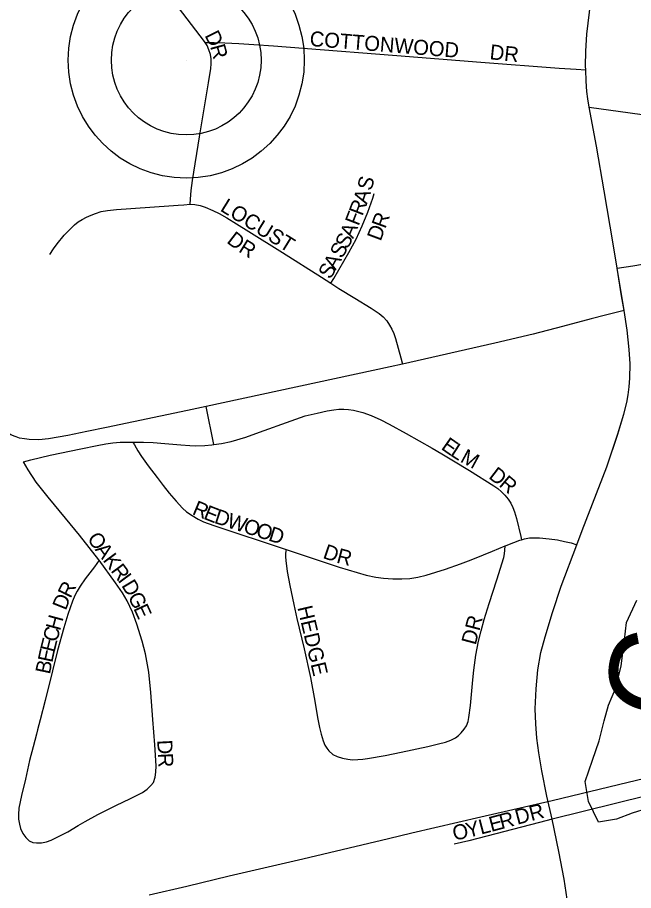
# Model space of a CAD drawing. Extents: x 1410790 to 1770854, y 566777 to 831614.
# Drawn here: x 1585877 to 1587927, y 704996 to 707901 of the extents above; entities that cross this region are included whole.
import ezdxf

# ---------------------------------------------------------------- set-up
doc = ezdxf.new("R2010")
doc.units = 0
for name, color, linetype in [('GM_X_City_Street', 7, 'Continuous'), ('GM_X_Corporation', 7, 'Continuous'), ('GM_X_County_Road', 7, 'Continuous'), ('GM_X_County_Road_Text', 7, 'Continuous'), ('GM_X_Minor_River', 7, 'Continuous'), ('GM_X_Rail_Line', 7, 'Continuous'), ('GM_X_Township_Subdivision', 7, 'Continuous'), ('GM_X_Township_Subdivision_Text', 7, 'Continuous'), ('GM_X_Unincorporated', 7, 'Continuous'), ('GM_X_Unincorporated_Location', 7, 'Continuous')]:
    doc.layers.add(name, color=color, linetype=linetype)

msp = doc.modelspace()

# ---------------------------------------------------------------- linework, layer by layer
at = {"layer": 'GM_X_City_Street'}
msp.add_lwpolyline([(1587872.1, 707066.5), (1587923.8, 707075.1), (1588014.1, 707090.2)], dxfattribs=at)
at = {"layer": 'GM_X_Corporation'}
msp.add_lwpolyline([(1588288.3, 705389.6), (1587655.6, 705233.1), (1587637.8, 705310.2), (1587621.4, 705393.9), (1587611.2, 705454.2), (1587605, 705502.7), (1587601, 705551.2), (1587599.5, 705600.5), (1587602.6, 705667), (1587608.1, 705730.4), (1587618.3, 705787.5), (1587633.1, 705840.7), (1587656.6, 705921.3), (1587686.3, 706008.9), (1587738, 706146.5), (1587756, 706194.3), (1587837.3, 706405.6), (1587874.9, 706515.1), (1587894.8, 706581), (1587904, 706619.5), (1587908.5, 706645), (1587912.4, 706672.4), (1587914.8, 706701.4), (1587915.6, 706748.3), (1587912.4, 706796.8), (1587906, 706861.1), (1587895.2, 706926.2), (1587872.1, 707066.5), (1587871.8, 707068.3), (1587848.9, 707206.6), (1587829.3, 707324.9), (1587802.9, 707472.6), (1587779.4, 707602.7), (1588156.3, 707550.7)], dxfattribs=at)
at = {"layer": 'GM_X_County_Road'}
for points in [[(1587767.4, 707726.7), (1587766.8, 707739.3), (1587767.4, 707789.5), (1587771.3, 707846.2), (1587793.7, 708030.3), (1587820.4, 708230.3), (1587824.5, 708261.2)], [(1587872.1, 707066.5), (1587871.8, 707068.3), (1587848.9, 707206.6), (1587829.3, 707324.9), (1587802.9, 707472.6), (1587779.4, 707602.7), (1587774.4, 707630), (1587771.4, 707655.2), (1587768.9, 707689.2), (1587767.4, 707726.7)], [(1586504.2, 706606.8), (1586442.1, 706593.4), (1586173, 706537), (1586107.8, 706523.9), (1586043.8, 706510.5), (1585979.6, 706499), (1585947.5, 706496), (1585915.4, 706496.7), (1585899.5, 706498.7), (1585883.8, 706501.7), (1585872.2, 706505.2), (1585868.7, 706506.3), (1585854.4, 706512.6), (1585840.9, 706520.8), (1585815.4, 706540.6), (1585791.7, 706562.8), (1585758.7, 706598.7), (1585714.7, 706654.2), (1585598.5, 706808.4), (1585507.2, 706925), (1585418.7, 707042.2), (1585306.7, 707183.7), (1585284.6, 707211.2)], [(1587895.2, 706926.1), (1587887, 706974.8), (1587872.1, 707066.5)], [(1587895.2, 706926.1), (1587833, 706910.2), (1587785.4, 706898), (1587690.8, 706872.4), (1587593.2, 706847.8), (1587465.6, 706817.4), (1587158.4, 706747.9)], [(1587738, 706146.5), (1587756, 706194.4), (1587837.3, 706405.6), (1587874.9, 706515.2), (1587894.8, 706581), (1587904, 706619.5), (1587908.5, 706645), (1587912.4, 706672.4), (1587914.8, 706701.3), (1587915.6, 706748.3), (1587912.4, 706796.8), (1587906, 706861.1), (1587895.2, 706926.1)], [(1587158.4, 706747.9), (1587117, 706738.5), (1586504.2, 706606.8)], [(1587655.6, 705233.1), (1587637.8, 705310.2), (1587621.4, 705393.9), (1587611.2, 705454.2), (1587605, 705502.7), (1587601.1, 705551.2), (1587599.5, 705600.5), (1587602.6, 705667), (1587608.1, 705730.4), (1587618.2, 705787.5), (1587633.1, 705840.7), (1587656.6, 705921.3), (1587686.3, 706008.9), (1587738, 706146.5)], [(1587703.7, 704682.8), (1587706.7, 704719.5), (1587714.4, 704820.2), (1587714.7, 704869.2), (1587711.4, 704921.4), (1587705.9, 704966.7), (1587695.7, 705033.2), (1587677.7, 705126.3), (1587655.6, 705233.1)]]:
    msp.add_lwpolyline(points, dxfattribs=at)
at = {"layer": 'GM_X_Minor_River'}
msp.add_lwpolyline([(1587972.2, 705268.7), (1587922.1, 705253.1), (1587870.1, 705233.4), (1587810.1, 705223.8), (1587776.6, 705292.2), (1587765.2, 705358.4), (1587789.7, 705430.3), (1587812.2, 705494.3), (1587828.7, 705560.3), (1587843, 705612.3), (1587867.5, 705670.2), (1587886, 705744.2), (1587896.7, 705830.3), (1587903.1, 705888.4), (1587937.7, 705962.3)], dxfattribs=at)
at = {"layer": 'GM_X_Rail_Line'}
msp.add_lwpolyline([(1586314.4, 704981.6), (1586440.7, 705010.3), (1586581.4, 705044.5), (1586825.9, 705101), (1587111.5, 705168.8), (1587189, 705188.3), (1587418, 705241.3), (1587656.2, 705296), (1587909.3, 705356.5), (1588113, 705405.4)], dxfattribs=at)
at = {"layer": 'GM_X_Township_Subdivision'}
for points in [[(1586501, 707818.4), (1586499.2, 707821.5), (1586383.7, 707973.6), (1586333.5, 708045.2), (1586296.5, 708099.5), (1586270.4, 708141.3), (1586252.8, 708173.1)], [(1586451.1, 707279.8), (1586452.1, 707296.4), (1586454.6, 707326), (1586458.6, 707358.8), (1586482, 707504.2), (1586512.6, 707683.9), (1586520.5, 707731.4), (1586521.4, 707747.3), (1586520.9, 707763.1), (1586518.4, 707778.6), (1586513.9, 707793.6), (1586507.4, 707807.9), (1586501, 707818.4)], [(1586501, 707818.4), (1586531.6, 707817.8), (1586566.2, 707816.9), (1586613.2, 707814.6), (1586662.7, 707811.7), (1586728.6, 707807), (1586827.1, 707798.9), (1587138.8, 707774.7), (1587418.2, 707752.1), (1587679.5, 707733.1), (1587736.3, 707729), (1587767.4, 707726.7)], [(1586919.8, 707016.6), (1586929.2, 707032.8), (1586979.4, 707118.8), (1587003.6, 707163.4), (1587023.8, 707208.1), (1587042.5, 707253.6), (1587058.9, 707300), (1587063.8, 707315.5)], [(1585984.5, 707112.7), (1585996.7, 707131.2), (1586009.2, 707148.4), (1586031.8, 707177.1), (1586052.5, 707198.2), (1586066.1, 707210.8), (1586078.6, 707220.7), (1586092.2, 707229.4), (1586106.8, 707237), (1586121.4, 707243.5), (1586136, 707249), (1586155.1, 707255.1), (1586176.3, 707259.1), (1586206.5, 707262.7), (1586379.9, 707273.9), (1586411.3, 707276.7), (1586430.4, 707278.2), (1586451.1, 707279.8)], [(1586451.1, 707279.8), (1586467.2, 707278.8), (1586484.3, 707275.7), (1586500.9, 707270.2), (1586526.6, 707259.1), (1586548.2, 707248.6), (1586573.4, 707234), (1586605.6, 707214.8), (1586646.3, 707189.2), (1586758, 707118.7), (1586887.9, 707036.7), (1586919.8, 707016.6)], [(1586919.8, 707016.6), (1586946.3, 706999.9), (1586999.6, 706967.7), (1587054, 706933.5), (1587079.7, 706915.9), (1587093.2, 706904.8), (1587105.3, 706891.7), (1587114.9, 706877.1), (1587122.4, 706863.5), (1587129, 706849.4), (1587135, 706833.4), (1587152.6, 706768.9), (1587158.4, 706747.9)], [(1586530.2, 706480.6), (1586504.2, 706606.8)], [(1586530.2, 706480.6), (1586555.2, 706483.8), (1586587.2, 706490.1), (1586636.9, 706504.5), (1586682.4, 706521.1), (1586787.7, 706559.4), (1586834, 706575.2), (1586873.5, 706585), (1586906.8, 706592.8), (1586929, 706596.1), (1586945.9, 706597.8), (1586962.2, 706597.9), (1586978.6, 706596.9), (1586994.9, 706594.6), (1587025.4, 706587.2), (1587053.9, 706576.5), (1587086.2, 706562.2), (1587113.4, 706548.4), (1587170.2, 706517.3), (1587256.7, 706468.4), (1587289, 706448.9), (1587327.8, 706426.1), (1587381.2, 706393.9), (1587461.3, 706343.1), (1587474.7, 706333.5), (1587487.3, 706322.9), (1587498.8, 706311.3), (1587509.2, 706298.7), (1587518, 706285), (1587525.5, 706270.6), (1587531.1, 706255.6), (1587537.2, 706234.5), (1587551.7, 706174), (1587554.2, 706163.4)], [(1585896.2, 706422.6), (1585921.5, 706428.9), (1585985.3, 706445), (1586087.5, 706466.1), (1586141.4, 706477.3), (1586170.3, 706482.8), (1586193.6, 706486.1), (1586218.6, 706487.8), (1586260.9, 706488.4)], [(1586260.9, 706488.4), (1586295.8, 706487.8), (1586328.1, 706486.7), (1586367.5, 706483.7), (1586420.3, 706478.9), (1586450.2, 706476.7), (1586470.3, 706475.6), (1586500.2, 706477.3), (1586522.9, 706479.6), (1586530.2, 706480.6)], [(1586260.9, 706488.4), (1586265.9, 706479.5), (1586276.9, 706459.5), (1586289.7, 706440), (1586311.7, 706409.4), (1586341.5, 706370.1), (1586361.7, 706344.3), (1586381.8, 706318.7), (1586404.7, 706291.2), (1586425.8, 706268.4), (1586439.1, 706256.2), (1586457.5, 706243.4), (1586478, 706231.8), (1586495.8, 706223.4), (1586529.7, 706210.6), (1586770.8, 706130.3)], [(1586148.3, 706094.8), (1586147.1, 706096.5), (1586082.8, 706178.7), (1586036.4, 706234.8), (1585978.6, 706304.8), (1585938.8, 706355.2), (1585911.9, 706395.9), (1585896.2, 706422.6)], [(1587499.7, 706142.8), (1587502.3, 706143.9), (1587527.8, 706154), (1587548.4, 706161.7), (1587554.2, 706163.4)], [(1587554.2, 706163.4), (1587563.9, 706166.2), (1587580.6, 706169.5), (1587597.2, 706170.1), (1587613.3, 706170.1), (1587646.1, 706166.8), (1587673.9, 706162.9), (1587697.2, 706157.9), (1587718.9, 706153.1), (1587738, 706146.5)], [(1586770.8, 706130.3), (1586768.5, 706118.4), (1586768, 706106.2), (1586769.1, 706094), (1586774.1, 706057.3), (1586782.9, 706011.2), (1586796.3, 705947.9), (1586806.3, 705901.2), (1586830.7, 705800.2), (1586851.3, 705705.2), (1586865.7, 705625.8), (1586875.2, 705571.3), (1586881.8, 705538), (1586887.4, 705516.3), (1586893.5, 705494.1), (1586899.1, 705480.2), (1586905.9, 705469.3), (1586912.4, 705460.8), (1586926.3, 705449.1), (1586940.1, 705442.5), (1586958.5, 705436.4), (1586976.3, 705433), (1586991.2, 705431.4), (1587009.1, 705432.4), (1587025.3, 705433.5), (1587041.4, 705435.4), (1587100.7, 705445.8), (1587153.9, 705456.3), (1587241.7, 705474.7), (1587277.3, 705483.6), (1587301.2, 705490.2), (1587318.4, 705496.3), (1587334.5, 705504.1), (1587343.9, 705511.4), (1587353.4, 705520.2), (1587363.4, 705532.4), (1587370.6, 705544.1), (1587376.2, 705558), (1587378.4, 705571.3), (1587384.4, 705611.2), (1587391.9, 705697.2), (1587394.9, 705729.7), (1587402.3, 705779.1), (1587411.2, 705826.3), (1587419.5, 705859.6), (1587430, 705897.4), (1587446.2, 705950.6), (1587472.3, 706029.6), (1587495.6, 706104.4), (1587497.3, 706116.8), (1587498.4, 706128.4), (1587499.7, 706142.8)], [(1586770.8, 706130.3), (1586946.8, 706071.8), (1587036.8, 706045.1), (1587069, 706038.5), (1587095.1, 706035.7), (1587126.2, 706033.5), (1587155.7, 706032.9), (1587181.8, 706034), (1587209, 706038.5), (1587236.8, 706045.1), (1587300.6, 706065.1), (1587350.6, 706082.9), (1587386.1, 706096.5), (1587427.4, 706113.1), (1587457.3, 706125.8), (1587499.7, 706142.8)], [(1586148.3, 706094.8), (1586132.5, 706073.6), (1586101.5, 706033.1), (1586085.5, 706008.7), (1586074.7, 705991.8), (1586067.7, 705978.1), (1586059.7, 705958.9), (1586043.9, 705914.9), (1586030.3, 705869.8), (1586009.9, 705794.2), (1585992.9, 705727), (1585968.3, 705628.4), (1585952.6, 705563.7), (1585943.3, 705531.1), (1585940, 705516.6), (1585929.1, 705474), (1585916.9, 705428.2), (1585902.8, 705366.6), (1585890.1, 705312.2), (1585880.9, 705270.3), (1585879.6, 705248.8), (1585880.3, 705233.5), (1585882.9, 705217.2), (1585886.8, 705202.8), (1585894, 705186.2), (1585904.4, 705172.4), (1585915.4, 705161.8)], [(1585915.4, 705161.8), (1585927.2, 705155.8), (1585939.9, 705154.2), (1585956.9, 705154.6), (1585972.9, 705158.1), (1585988.3, 705163.6), (1586004.6, 705171.1), (1586044.7, 705191), (1586078.8, 705212.7), (1586101.4, 705226.1), (1586144.1, 705248.5), (1586188, 705271.1), (1586204.3, 705279.1), (1586252.3, 705302.2), (1586292.6, 705322.4), (1586308.2, 705333.5), (1586320.9, 705344.9), (1586329.1, 705355.8), (1586335.2, 705373.7), (1586337.4, 705389.3), (1586337.7, 705410.8), (1586333.4, 705480.7), (1586326.8, 705565.5), (1586320.9, 705655.2), (1586313.9, 705723), (1586302.5, 705783.2), (1586291.1, 705826.3), (1586274, 705882.5), (1586259.3, 705922.4), (1586241.4, 705959.8), (1586226, 705986.6), (1586203.2, 706020), (1586148.3, 706094.8)], [(1587655.6, 705233.1), (1587614, 705222.7), (1587378.9, 705161.6), (1587330.3, 705150.6)]]:
    msp.add_lwpolyline(points, dxfattribs=at)
at = {"layer": 'GM_X_Unincorporated'}
for radius in [392.8, 249]:
    msp.add_circle((1586438.2, 707759.3), radius, dxfattribs=at)
at = {"layer": 'GM_X_Unincorporated_Location'}
msp.add_line((1586438.2, 707759.3), (1586438.2, 707759.3), dxfattribs=at)

# ---------------------------------------------------------------- texts
at = {"layer": 'GM_X_County_Road_Text'}
msp.add_text('C', height=300, rotation=80.6178, dxfattribs=at).set_placement((1588120.5, 705548.4))
at = {"layer": 'GM_X_Township_Subdivision_Text'}
for s, rotation, p in [('D', 296.6042, (1586498.4, 707842)), ('COTTONWOOD', 355.4263, (1586847.7, 707806.5)), ('R', 285.4851, (1586517.2, 707805.1)), ('DR', 353.9832, (1587446.3, 707762.5)), ('S', 74.9491, (1587054.3, 707322.4)), ('A', 71.2723, (1587039.2, 707277.4)), ('LOCUST', 328.3223, (1586548.2, 707259.6)), ('R', 68.9295, (1587024.2, 707238.4)), ('F', 68.8823, (1587011.5, 707205.5)), ('R', 70.0092, (1587100.6, 707196.2)), ('A', 66.7138, (1586993.3, 707163.2)), ('D', 69.4772, (1587085, 707154.6)), ('D', 322.3781, (1586570.1, 707153.5)), ('S', 61.349, (1586974.2, 707127.7)), ('R', 328.1663, (1586609.4, 707123.5)), ('S', 60.7092, (1586956.7, 707096.4)), ('A', 60.726, (1586935.2, 707058.1)), ('S', 60.7092, (1586918, 707027.4)), ('E', 324.999, (1587283.5, 706466.5)), ('L', 327.0936, (1587314, 706445.2)), ('M', 331.3196, (1587346.9, 706424.1)), ('D', 322.5793, (1587441.7, 706369.8)), ('R', 319.8991, (1587476.2, 706343.5)), ('R', 337.3913, (1586455.3, 706249.3)), ('E', 338.3058, (1586492.7, 706233.8)), ('D', 341.6713, (1586528.4, 706219.7)), ('W', 342.1857, (1586570.6, 706205.7)), ('O', 342.2125, (1586625.1, 706188.2)), ('O', 342.2125, (1586667, 706174.7)), ('O', 306.564, (1586106.5, 706166)), ('D', 342.2202, (1586708.9, 706161.3)), ('A', 306.5464, (1586132.7, 706130.6)), ('D', 341.0328, (1586889.9, 706103.1)), ('R', 345.4738, (1586935.5, 706087.6)), ('K', 306.5787, (1586158.9, 706095.2)), ('R', 306.5813, (1586185.1, 706059.9)), ('I', 306.564, (1586208.7, 706028.1)), ('R', 64.2277, (1586053.3, 705966)), ('D', 300.7726, (1586221.1, 706011.5)), ('G', 294.9034, (1586243, 705974.9)), ('D', 68.2108, (1586037.3, 705925.9)), ('E', 294.6339, (1586261.5, 705935.1)), ('HEDGE', 283.1753, (1586807.8, 705937.9)), ('H', 74.9404, (1586018.2, 705858.3)), ('DR', 75.2542, (1587401.1, 705810.7)), ('C', 75.0154, (1586008, 705820.1)), ('E', 76.1758, (1585999.7, 705786.2)), ('E', 77.8594, (1585992.3, 705752.2)), ('B', 78.0375, (1585984.2, 705713.5)), ('D', 272.9737, (1586341.5, 705496.4)), ('R', 272.8187, (1586343.8, 705452.5)), ('R', 14.8198, (1587487, 705199.8)), ('DR', 14.7487, (1587539.8, 705214.6)), ('Y', 13.8976, (1587375.4, 705171)), ('L', 14.8096, (1587418.9, 705181.8)), ('E', 14.8242, (1587453, 705190.8)), ('O', 10.9285, (1587329.4, 705162))]:
    msp.add_text(s, height=50, rotation=rotation, dxfattribs=at).set_placement(p)

doc.saveas('drawing.dxf')
